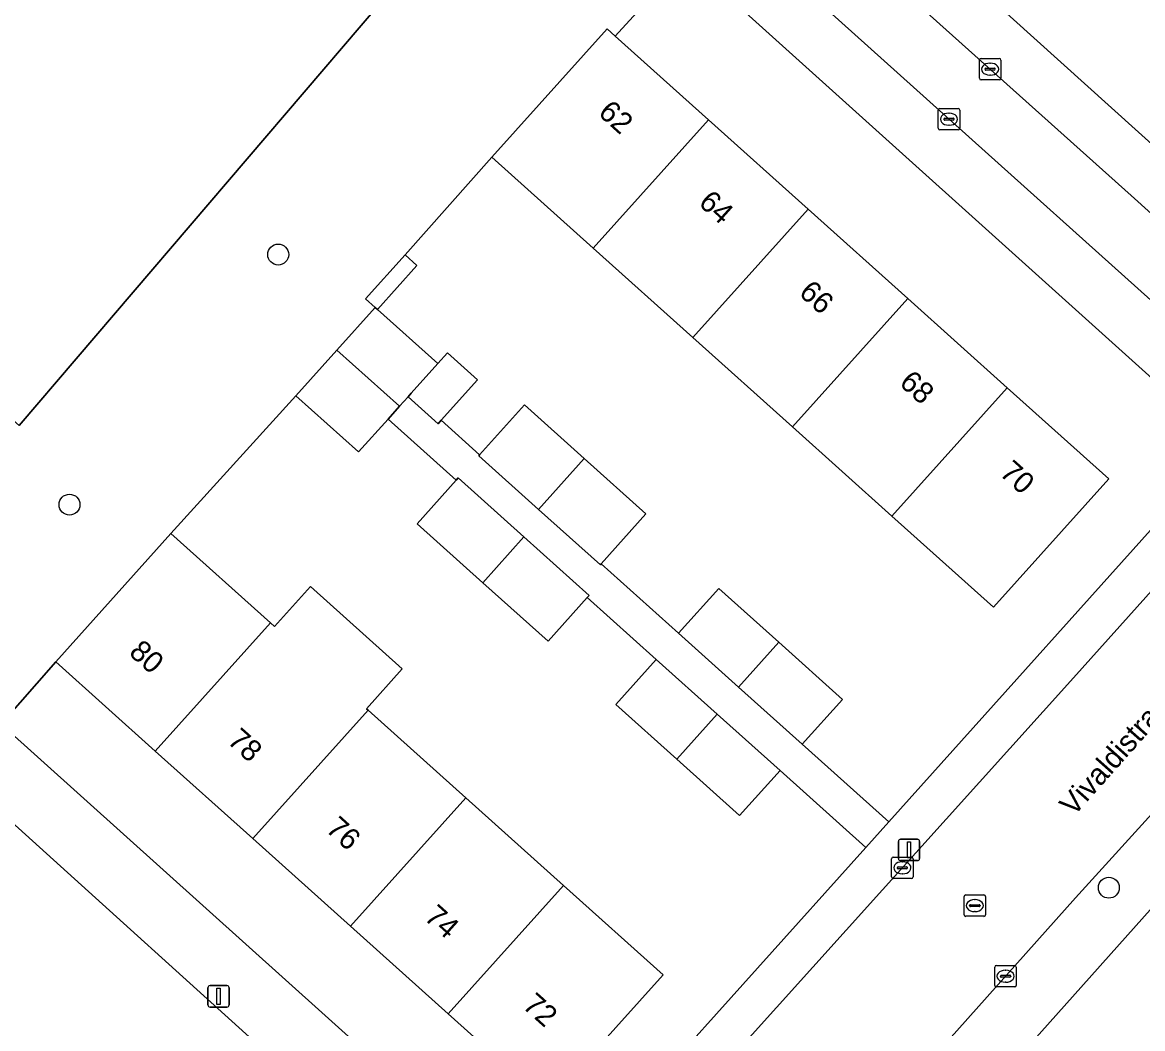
# Model space of a CAD drawing. Extents: x 159039 to 160102, y 381214 to 382524.
# Drawn here: x 159387.5 to 159439.8, y 382041.4 to 382088.4 of the extents above; entities that cross this region are included whole.
import ezdxf

# ---------------------------------------------------------------- set-up
doc = ezdxf.new("R2010")
doc.units = 0
for name, color, linetype in [('IMGEO_Boom', 7, 'Continuous'), ('IMGEO_Erf', 7, 'Continuous'), ('IMGEO_Groenvoorziening', 7, 'Continuous'), ('IMGEO_Kolk', 7, 'Continuous'), ('IMGEO_Lichtmast', 7, 'Continuous'), ('IMGEO_Openbare_ruimte_label', 7, 'Continuous'), ('IMGEO_Pand', 7, 'Continuous'), ('IMGEO_Pand_nummerreeks', 7, 'Continuous'), ('IMGEO_Rijbaan_lokaal_open', 7, 'Continuous'), ('IMGEO_Rioolput', 7, 'Continuous'), ('IMGEO_Voetpad_open', 7, 'Continuous')]:
    doc.layers.add(name, color=color, linetype=linetype)

msp = doc.modelspace()

# ---------------------------------------------------------------- linework, layer by layer
at = {"layer": 'IMGEO_Boom'}
for centre in [(159399.463, 382077.601), (159389.717, 382065.92), (159438.25, 382048.027)]:
    msp.add_circle(centre, 0.489, dxfattribs=at)
at = {"layer": 'IMGEO_Erf'}
for points in [[(159447.332, 382104.853), (159444.401, 382107.483), (159446.182, 382109.469), (159442.855, 382112.454), (159441.607, 382111.063), (159438.669, 382113.699), (159432.686, 382107.057), (159437.336, 382102.884), (159441.895, 382098.793), (159446.455, 382094.7), (159451.014, 382090.609), (159455.662, 382086.437), (159450.321, 382080.486), (159445.673, 382084.658), (159441.114, 382088.749), (159436.554, 382092.841), (159431.994, 382096.933), (159427.345, 382101.105), (159424.019, 382097.413), (159447.998, 382075.782)], [(159442.459, 382069.847), (159418.503, 382091.427), (159418.239, 382091.137), (159415.202, 382087.803), (159419.558, 382083.893), (159424.207, 382079.721), (159428.857, 382075.549), (159433.506, 382071.376), (159438.245, 382067.123), (159432.861, 382061.124), (159428.122, 382065.377), (159423.473, 382069.55), (159418.824, 382073.722), (159414.174, 382077.895)], [(159414.174, 382077.895), (159409.437, 382082.146), (159405.385, 382077.591), (159405.942, 382077.09), (159404.099, 382075.036), (159406.915, 382072.509), (159407.364, 382073.009), (159408.769, 382071.748), (159407.076, 382069.862), (159408.87, 382068.251), (159410.959, 382070.579), (159413.753, 382068.071), (159416.636, 382065.484), (159414.547, 382063.157), (159418.156, 382059.917), (159420.036, 382062.011), (159422.841, 382059.493), (159425.817, 382056.823), (159423.937, 382054.728), (159427.974, 382051.104), (159442.778, 382067.615)], [(159411.732, 382032.989), (159426.898, 382049.904), (159422.895, 382053.498), (159421.008, 382051.396), (159418.078, 382054.026), (159415.224, 382056.587), (159417.111, 382058.689), (159413.893, 382061.576), (159412.063, 382059.538), (159409.013, 382062.275), (159405.946, 382065.027), (159407.775, 382067.064), (159404.591, 382069.92), (159403.21, 382068.38), (159400.284, 382071.006), (159394.457, 382064.578), (159399.104, 382060.407), (159399.294, 382060.236), (159400.968, 382062.1), (159405.254, 382058.253), (159403.58, 382056.389), (159403.664, 382056.314), (159408.225, 382052.222), (159412.785, 382048.128), (159417.434, 382043.956), (159412.054, 382037.961), (159407.405, 382042.133), (159402.844, 382046.226), (159398.284, 382050.319), (159393.724, 382054.412), (159389.076, 382058.583), (159386.52, 382055.672), (159411.223, 382033.447)], [(159440.696, 382047.571), (159420.759, 382025.224)]]:
    msp.add_lwpolyline(points, dxfattribs=at)
at = {"layer": 'IMGEO_Groenvoorziening'}
for points in [[(159394.028, 382114.374), (159390.166, 382108.397), (159385.031, 382100.107), (159373.992, 382081.27), (159377.887, 382077.878), (159385.857, 382070.936), (159387.365, 382069.622), (159408.66, 382094.544)], [(159418.2, 382095.331), (159416.462, 382097.35), (159413.377, 382100.065), (159408.66, 382094.544), (159387.365, 382069.622), (159385.857, 382070.936), (159378.221, 382062.169), (159386.063, 382055.21), (159386.52, 382055.672), (159389.076, 382058.583), (159394.457, 382064.578), (159400.284, 382071.006), (159402.2, 382073.142), (159403.989, 382075.135), (159403.541, 382075.537), (159405.385, 382077.591)], [(159405.385, 382077.591), (159409.437, 382082.146), (159414.821, 382088.145), (159415.202, 382087.803), (159418.239, 382091.137), (159417.632, 382091.692), (159418.453, 382092.583)], [(159389.664, 382026.24), (159392.524, 382025.185), (159399.138, 382033.039), (159402.528, 382037.064), (159384.382, 382053.472)]]:
    msp.add_lwpolyline(points, dxfattribs=at)
at = {"layer": 'IMGEO_Kolk'}
for p, q in [((159432.206, 382085.838), (159432.206, 382086.69)), ((159432.281, 382086.764), (159433.133, 382086.764)), ((159432.465, 382086.258), (159432.465, 382086.27)), ((159432.508, 382086.307), (159432.906, 382086.307)), ((159432.694, 382086.544), (159432.719, 382086.544)), ((159432.949, 382086.27), (159432.949, 382086.258)), ((159433.207, 382086.69), (159433.207, 382085.838)), ((159433.133, 382085.764), (159432.281, 382085.764)), ((159432.903, 382086.221), (159432.505, 382086.221)), ((159432.717, 382085.984), (159432.692, 382085.984)), ((159430.285, 382083.5), (159430.285, 382084.352)), ((159430.36, 382084.426), (159431.212, 382084.426)), ((159430.773, 382084.206), (159430.798, 382084.206)), ((159431.286, 382084.352), (159431.286, 382083.5)), ((159430.544, 382083.92), (159430.544, 382083.932)), ((159430.982, 382083.883), (159430.584, 382083.883)), ((159430.587, 382083.969), (159430.985, 382083.969)), ((159430.796, 382083.646), (159430.771, 382083.646)), ((159431.028, 382083.932), (159431.028, 382083.92)), ((159431.212, 382083.426), (159430.36, 382083.426)), ((159428.107, 382048.53), (159428.107, 382049.382)), ((159428.182, 382049.456), (159429.034, 382049.456)), ((159428.595, 382049.236), (159428.62, 382049.236)), ((159429.108, 382049.382), (159429.108, 382048.53)), ((159428.366, 382048.95), (159428.366, 382048.962)), ((159428.804, 382048.913), (159428.406, 382048.913)), ((159428.409, 382048.999), (159428.807, 382048.999)), ((159428.618, 382048.676), (159428.593, 382048.676)), ((159428.85, 382048.962), (159428.85, 382048.95)), ((159429.034, 382048.456), (159428.182, 382048.456)), ((159432.926, 382043.466), (159432.926, 382044.318)), ((159433.001, 382044.392), (159433.853, 382044.392)), ((159433.185, 382043.886), (159433.185, 382043.898)), ((159433.228, 382043.935), (159433.626, 382043.935)), ((159433.414, 382044.172), (159433.439, 382044.172)), ((159433.669, 382043.898), (159433.669, 382043.886)), ((159433.927, 382044.318), (159433.927, 382043.466)), ((159433.853, 382043.392), (159433.001, 382043.392)), ((159433.623, 382043.849), (159433.225, 382043.849)), ((159433.437, 382043.612), (159433.412, 382043.612))]:
    msp.add_line(p, q, dxfattribs=at)
for points in [[(159432.206, 382085.838), (159432.206, 382086.69)], [(159432.281, 382086.764), (159433.133, 382086.764)], [(159433.207, 382086.69), (159433.207, 382085.838)], [(159433.133, 382085.764), (159432.281, 382085.764)], [(159430.285, 382083.5), (159430.285, 382084.352)], [(159430.36, 382084.426), (159431.212, 382084.426)], [(159431.286, 382084.352), (159431.286, 382083.5)], [(159431.212, 382083.426), (159430.36, 382083.426)], [(159428.107, 382048.53), (159428.107, 382049.382)], [(159428.182, 382049.456), (159429.034, 382049.456)], [(159429.108, 382049.382), (159429.108, 382048.53)], [(159429.034, 382048.456), (159428.182, 382048.456)], [(159432.926, 382043.466), (159432.926, 382044.318)], [(159433.001, 382044.392), (159433.853, 382044.392)], [(159433.927, 382044.318), (159433.927, 382043.466)], [(159433.853, 382043.392), (159433.001, 382043.392)]]:
    msp.add_lwpolyline(points, dxfattribs=at)
for centre, radius, start, end in [((159432.283, 382086.688), 0.0765, 91.552, 178.448), ((159432.283, 382086.688), 0.0765, 91.552, 178.448), ((159432.505, 382086.267), 0.0403, 85.8775, 175.7526), ((159432.502, 382086.257), 0.0366, 178.938, 274.7102), ((159432.906, 382086.264), 0.043, 264.8664, 352.4533), ((159432.91, 382086.269), 0.0386, 1.7309, 96.639), ((159433.131, 382086.688), 0.0765, 1.552, 88.448), ((159433.131, 382086.688), 0.0765, 1.552, 88.448), ((159432.283, 382085.84), 0.0765, 181.552, 268.448), ((159432.283, 382085.84), 0.0765, 181.552, 268.448), ((159433.131, 382085.84), 0.0765, 271.552, 358.448), ((159433.131, 382085.84), 0.0765, 271.552, 358.448), ((159430.362, 382084.35), 0.0765, 91.552, 178.448), ((159430.362, 382084.35), 0.0765, 91.552, 178.448), ((159431.21, 382084.35), 0.0765, 1.552, 88.448), ((159431.21, 382084.35), 0.0765, 1.552, 88.448), ((159430.584, 382083.929), 0.0403, 85.8775, 175.7526), ((159430.581, 382083.919), 0.0366, 178.938, 274.7102), ((159430.985, 382083.926), 0.043, 264.8664, 352.4533), ((159430.989, 382083.931), 0.0386, 1.7309, 96.639), ((159430.362, 382083.502), 0.0765, 181.552, 268.448), ((159430.362, 382083.502), 0.0765, 181.552, 268.448), ((159431.21, 382083.502), 0.0765, 271.552, 358.448), ((159431.21, 382083.502), 0.0765, 271.552, 358.448), ((159428.184, 382049.38), 0.0765, 91.552, 178.448), ((159428.184, 382049.38), 0.0765, 91.552, 178.448), ((159429.032, 382049.38), 0.0765, 1.552, 88.448), ((159429.032, 382049.38), 0.0765, 1.552, 88.448), ((159428.406, 382048.959), 0.0403, 85.8775, 175.7526), ((159428.403, 382048.949), 0.0366, 178.938, 274.7102), ((159428.807, 382048.956), 0.043, 264.8664, 352.4533), ((159428.811, 382048.961), 0.0386, 1.7309, 96.639), ((159428.184, 382048.532), 0.0765, 181.552, 268.448), ((159428.184, 382048.532), 0.0765, 181.552, 268.448), ((159429.032, 382048.532), 0.0765, 271.552, 358.448), ((159429.032, 382048.532), 0.0765, 271.552, 358.448), ((159433.003, 382044.316), 0.0765, 91.552, 178.448), ((159433.003, 382044.316), 0.0765, 91.552, 178.448), ((159433.225, 382043.895), 0.0403, 85.8775, 175.7526), ((159433.222, 382043.885), 0.0366, 178.938, 274.7102), ((159433.626, 382043.892), 0.043, 264.8664, 352.4533), ((159433.63, 382043.897), 0.0386, 1.7309, 96.639), ((159433.851, 382044.316), 0.0765, 1.552, 88.448), ((159433.851, 382044.316), 0.0765, 1.552, 88.448), ((159433.003, 382043.468), 0.0765, 181.552, 268.448), ((159433.003, 382043.468), 0.0765, 181.552, 268.448), ((159433.851, 382043.468), 0.0765, 271.552, 358.448), ((159433.851, 382043.468), 0.0765, 271.552, 358.448)]:
    msp.add_arc(centre, radius, start, end, dxfattribs=at)
for centre, major_axis, ratio, start_param, end_param in [((159432.693, 382086.264), (-0.387, 0.002), 0.722429, 4.712389, 7.853982), ((159432.718, 382086.264), (-0.39, 0.002), 0.717154, 1.570796, 4.712389), ((159430.772, 382083.926), (-0.387, 0.002), 0.722429, 4.712389, 7.853982), ((159430.797, 382083.926), (-0.39, 0.002), 0.717154, 1.570796, 4.712389), ((159428.594, 382048.956), (-0.387, 0.002), 0.722429, 4.712389, 7.853982), ((159428.619, 382048.956), (-0.39, 0.002), 0.717154, 1.570796, 4.712389), ((159433.413, 382043.892), (-0.387, 0.002), 0.722429, 4.712389, 7.853982), ((159433.438, 382043.892), (-0.39, 0.002), 0.717154, 1.570796, 4.712389)]:
    msp.add_ellipse(centre, major_axis=major_axis, ratio=ratio, start_param=start_param, end_param=end_param, dxfattribs=at)
at = {"layer": 'IMGEO_Lichtmast'}
for p, q in [((159428.423, 382049.39), (159428.423, 382050.19)), ((159428.423, 382050.19), (159428.423, 382049.39)), ((159428.523, 382050.29), (159429.313, 382050.29)), ((159429.313, 382050.29), (159428.523, 382050.29)), ((159429.413, 382050.19), (159429.413, 382049.39)), ((159429.413, 382049.39), (159429.413, 382050.19)), ((159429.313, 382049.29), (159428.523, 382049.29)), ((159428.523, 382049.29), (159429.313, 382049.29)), ((159396.279, 382043.453), (159397.069, 382043.453)), ((159397.069, 382043.453), (159396.279, 382043.453)), ((159396.179, 382042.553), (159396.179, 382043.353)), ((159396.179, 382043.353), (159396.179, 382042.553)), ((159397.169, 382043.353), (159397.169, 382042.553)), ((159397.169, 382042.553), (159397.169, 382043.353)), ((159397.069, 382042.453), (159396.279, 382042.453)), ((159396.279, 382042.453), (159397.069, 382042.453))]:
    msp.add_line(p, q, dxfattribs=at)
for points in [[(159428.843, 382050.165), (159428.993, 382050.165), (159428.993, 382049.415), (159428.843, 382049.415), (159428.843, 382050.165)], [(159396.599, 382043.328), (159396.749, 382043.328), (159396.749, 382042.578), (159396.599, 382042.578), (159396.599, 382043.328)]]:
    msp.add_lwpolyline(points, dxfattribs=at)
for centre, start, end in [((159428.523, 382050.19), 90, 180), ((159428.523, 382050.19), 90, 180), ((159429.313, 382050.19), 0, 90), ((159429.313, 382050.19), 360, 90), ((159428.523, 382049.39), 180, 270), ((159428.523, 382049.39), 180, 270), ((159429.313, 382049.39), 270, 0), ((159429.313, 382049.39), 270, 0), ((159396.279, 382043.353), 90, 180), ((159396.279, 382043.353), 90, 180), ((159397.069, 382043.353), 0, 90), ((159397.069, 382043.353), 360, 90), ((159396.279, 382042.553), 180, 270), ((159396.279, 382042.553), 180, 270), ((159397.069, 382042.553), 270, 0), ((159397.069, 382042.553), 270, 0)]:
    msp.add_arc(centre, 0.1, start, end, dxfattribs=at)
at = {"layer": 'IMGEO_Pand'}
for points in [[(159414.174, 382077.895), (159419.558, 382083.893), (159415.202, 382087.803), (159414.821, 382088.145), (159409.437, 382082.146)], [(159418.824, 382073.722), (159424.207, 382079.721), (159419.558, 382083.893), (159414.174, 382077.895)], [(159418.824, 382073.722), (159423.473, 382069.55), (159428.857, 382075.549), (159424.207, 382079.721)], [(159405.942, 382077.09), (159405.385, 382077.591), (159403.541, 382075.537), (159403.989, 382075.135), (159404.099, 382075.036)], [(159428.122, 382065.377), (159433.506, 382071.376), (159428.857, 382075.549), (159423.473, 382069.55)], [(159404.099, 382075.036), (159403.989, 382075.135), (159402.2, 382073.142), (159405.127, 382070.517), (159405.525, 382070.961), (159405.671, 382071.123), (159406.915, 382072.509)], [(159402.2, 382073.142), (159400.284, 382071.006), (159403.21, 382068.38), (159404.591, 382069.92), (159405.127, 382070.517)], [(159406.915, 382072.509), (159405.671, 382071.123), (159405.525, 382070.961), (159406.93, 382069.699), (159407.076, 382069.862), (159408.769, 382071.748), (159407.364, 382073.009)], [(159428.122, 382065.377), (159432.861, 382061.124), (159438.245, 382067.123), (159433.506, 382071.376)], [(159408.87, 382068.251), (159408.828, 382068.204), (159411.622, 382065.696), (159413.753, 382068.071), (159410.959, 382070.579)], [(159413.753, 382068.071), (159411.622, 382065.696), (159414.505, 382063.11), (159414.547, 382063.157), (159416.636, 382065.484)], [(159407.775, 382067.064), (159405.946, 382065.027), (159409.013, 382062.275), (159410.936, 382064.417), (159407.869, 382067.169)], [(159399.104, 382060.407), (159394.457, 382064.578), (159389.076, 382058.583), (159393.724, 382054.412)], [(159410.936, 382064.417), (159409.013, 382062.275), (159412.063, 382059.538), (159413.893, 382061.576), (159413.986, 382061.68)], [(159403.664, 382056.314), (159403.58, 382056.389), (159405.254, 382058.253), (159400.968, 382062.1), (159399.294, 382060.236), (159399.104, 382060.407), (159393.724, 382054.412), (159398.284, 382050.319)], [(159420.962, 382057.399), (159422.841, 382059.493), (159420.036, 382062.011), (159418.156, 382059.917)], [(159420.962, 382057.399), (159423.937, 382054.728), (159425.817, 382056.823), (159422.841, 382059.493)], [(159418.078, 382054.026), (159419.964, 382056.128), (159417.111, 382058.689), (159415.224, 382056.587)], [(159402.844, 382046.226), (159408.225, 382052.222), (159403.664, 382056.314), (159398.284, 382050.319)], [(159418.078, 382054.026), (159421.008, 382051.396), (159422.895, 382053.498), (159419.964, 382056.128)], [(159402.844, 382046.226), (159407.405, 382042.133), (159412.785, 382048.128), (159408.225, 382052.222)], [(159407.405, 382042.133), (159412.054, 382037.961), (159417.434, 382043.956), (159412.785, 382048.128)]]:
    msp.add_lwpolyline(points, close=True, dxfattribs=at)
at = {"layer": 'IMGEO_Rijbaan_lokaal_open'}
msp.add_lwpolyline([(159484.51, 382111.174), (159481.021, 382107.349), (159474.838, 382100.428), (159466.594, 382091.206), (159459.375, 382083.3), (159449.46, 382072.146), (159446.424, 382068.776), (159443.761, 382065.82), (159436.593, 382057.833), (159429.233, 382049.65), (159421.179, 382040.701), (159414.041, 382032.697), (159412.333, 382030.791), (159417.471, 382026.041), (159418.427, 382027.145), (159421.101, 382030.063), (159436.695, 382047.561), (159444.758, 382056.431), (159447.825, 382059.867), (159456.22, 382069.32), (159461.578, 382075.157), (159466.546, 382080.765), (159473.262, 382088.194)], dxfattribs=at)
msp.add_lwpolyline([(159426.476, 382091.859), (159422.172, 382095.85), (159421.139, 382094.706), (159420.122, 382093.578), (159424.405, 382089.668), (159432.474, 382082.409), (159445.513, 382070.713), (159447.544, 382072.913), (159439.286, 382080.355)], close=True, dxfattribs=at)
at = {"layer": 'IMGEO_Rioolput'}
for p, q in [((159431.491, 382046.764), (159431.491, 382047.616)), ((159431.566, 382047.69), (159432.418, 382047.69)), ((159432.492, 382047.616), (159432.492, 382046.764)), ((159431.75, 382047.184), (159431.75, 382047.196)), ((159432.188, 382047.147), (159431.79, 382047.147)), ((159431.793, 382047.233), (159432.191, 382047.233)), ((159431.979, 382047.47), (159432.004, 382047.47)), ((159432.234, 382047.196), (159432.234, 382047.184)), ((159432.418, 382046.69), (159431.566, 382046.69)), ((159432.002, 382046.91), (159431.977, 382046.91))]:
    msp.add_line(p, q, dxfattribs=at)
for points in [[(159431.491, 382046.764), (159431.491, 382047.616)], [(159431.566, 382047.69), (159432.418, 382047.69)], [(159432.492, 382047.616), (159432.492, 382046.764)], [(159432.418, 382046.69), (159431.566, 382046.69)]]:
    msp.add_lwpolyline(points, dxfattribs=at)
for centre, radius, start, end in [((159431.568, 382047.614), 0.0765, 91.552, 178.448), ((159431.568, 382047.614), 0.0765, 91.552, 178.448), ((159432.416, 382047.614), 0.0765, 1.552, 88.448), ((159432.416, 382047.614), 0.0765, 1.552, 88.448), ((159431.79, 382047.193), 0.0403, 85.8775, 175.7526), ((159431.787, 382047.183), 0.0366, 178.938, 274.7102), ((159432.191, 382047.19), 0.043, 264.8664, 352.4533), ((159432.195, 382047.195), 0.0386, 1.7309, 96.639), ((159431.568, 382046.766), 0.0765, 181.552, 268.448), ((159431.568, 382046.766), 0.0765, 181.552, 268.448), ((159432.416, 382046.766), 0.0765, 271.552, 358.448), ((159432.416, 382046.766), 0.0765, 271.552, 358.448)]:
    msp.add_arc(centre, radius, start, end, dxfattribs=at)
for centre, major_axis, ratio, start_param, end_param in [((159431.978, 382047.19), (-0.387, 0.002), 0.722429, 4.712389, 7.853982), ((159432.003, 382047.19), (-0.39, 0.002), 0.717154, 1.570796, 4.712389)]:
    msp.add_ellipse(centre, major_axis=major_axis, ratio=ratio, start_param=start_param, end_param=end_param, dxfattribs=at)
at = {"layer": 'IMGEO_Voetpad_open'}
for points in [[(159405.075, 382022.706), (159408.179, 382026.131), (159408.537, 382026.522), (159410.311, 382028.535), (159412.333, 382030.791), (159414.041, 382032.697), (159421.179, 382040.701), (159429.233, 382049.65), (159436.593, 382057.833), (159443.761, 382065.82), (159446.424, 382068.776), (159449.46, 382072.146), (159459.375, 382083.3), (159466.594, 382091.206), (159474.838, 382100.428), (159481.021, 382107.349), (159484.51, 382111.174)], [(159490.537, 382107.476), (159486.13, 382102.405), (159473.262, 382088.194), (159466.546, 382080.765), (159461.578, 382075.157), (159456.22, 382069.32), (159447.825, 382059.867), (159444.758, 382056.431), (159436.695, 382047.561), (159421.101, 382030.063), (159418.427, 382027.145), (159417.471, 382026.041)], [(159424.019, 382097.413), (159423.442, 382097.934), (159421.535, 382095.926), (159420.742, 382095.065), (159421.139, 382094.706), (159422.172, 382095.85), (159426.476, 382091.859), (159439.286, 382080.355), (159447.544, 382072.913), (159449.93, 382075.598)], [(159447.998, 382075.782), (159424.019, 382097.413)], [(159432.474, 382082.409), (159424.405, 382089.668), (159420.122, 382093.578), (159421.139, 382094.706), (159420.742, 382095.065), (159418.453, 382092.583), (159417.632, 382091.692), (159418.239, 382091.137), (159418.503, 382091.427), (159442.459, 382069.847)], [(159442.922, 382067.79), (159445.513, 382070.713), (159432.474, 382082.409)], [(159415.844, 382019.716), (159420.759, 382025.224), (159440.696, 382047.571), (159445.905, 382053.353), (159446.933, 382054.493), (159463.725, 382073.13)], [(159442.778, 382067.615), (159427.974, 382051.104), (159426.898, 382049.904), (159411.732, 382032.989), (159411.223, 382033.447), (159407.213, 382029.474)], [(159386.52, 382055.672), (159386.063, 382055.21), (159384.382, 382053.472), (159402.528, 382037.064), (159407.011, 382033.011)], [(159407.213, 382029.474), (159411.223, 382033.447), (159386.52, 382055.672)]]:
    msp.add_lwpolyline(points, dxfattribs=at)
msp.add_lwpolyline([(159414.547, 382063.157), (159414.505, 382063.11), (159411.622, 382065.696), (159408.828, 382068.204), (159408.87, 382068.251), (159407.076, 382069.862), (159406.93, 382069.699), (159405.525, 382070.961), (159405.127, 382070.517), (159404.591, 382069.92), (159407.775, 382067.064), (159407.869, 382067.169), (159410.936, 382064.417), (159413.986, 382061.68), (159413.893, 382061.576), (159417.111, 382058.689), (159419.964, 382056.128), (159422.895, 382053.498), (159426.898, 382049.904), (159427.974, 382051.104), (159423.937, 382054.728), (159420.962, 382057.399), (159418.156, 382059.917)], close=True, dxfattribs=at)

# ---------------------------------------------------------------- texts
at = {"layer": 'IMGEO_Openbare_ruimte_label'}
msp.add_text('Vivaldistraat', height=1, rotation=48.3236, dxfattribs=at).set_placement((159436.608, 382051.325))
at = {"layer": 'IMGEO_Pand_nummerreeks'}
for s, rotation, p in [('62', 318.0934, (159414.355, 382084.156)), ('64', 318.0934, (159419.042, 382079.949)), ('66', 318.0934, (159423.727, 382075.745)), ('68', 318.0934, (159428.414, 382071.538)), ('70', 318.0934, (159433.099, 382067.334)), ('80', 318.0931, (159392.444, 382058.946)), ('78', 318.0939, (159397.039, 382054.822)), ('76', 318.0931, (159401.633, 382050.699)), ('74', 318.0931, (159406.229, 382046.575)), ('72', 318.0931, (159410.822, 382042.452))]:
    msp.add_text(s, height=1, rotation=rotation, dxfattribs=at).set_placement(p)

doc.saveas('drawing.dxf')
